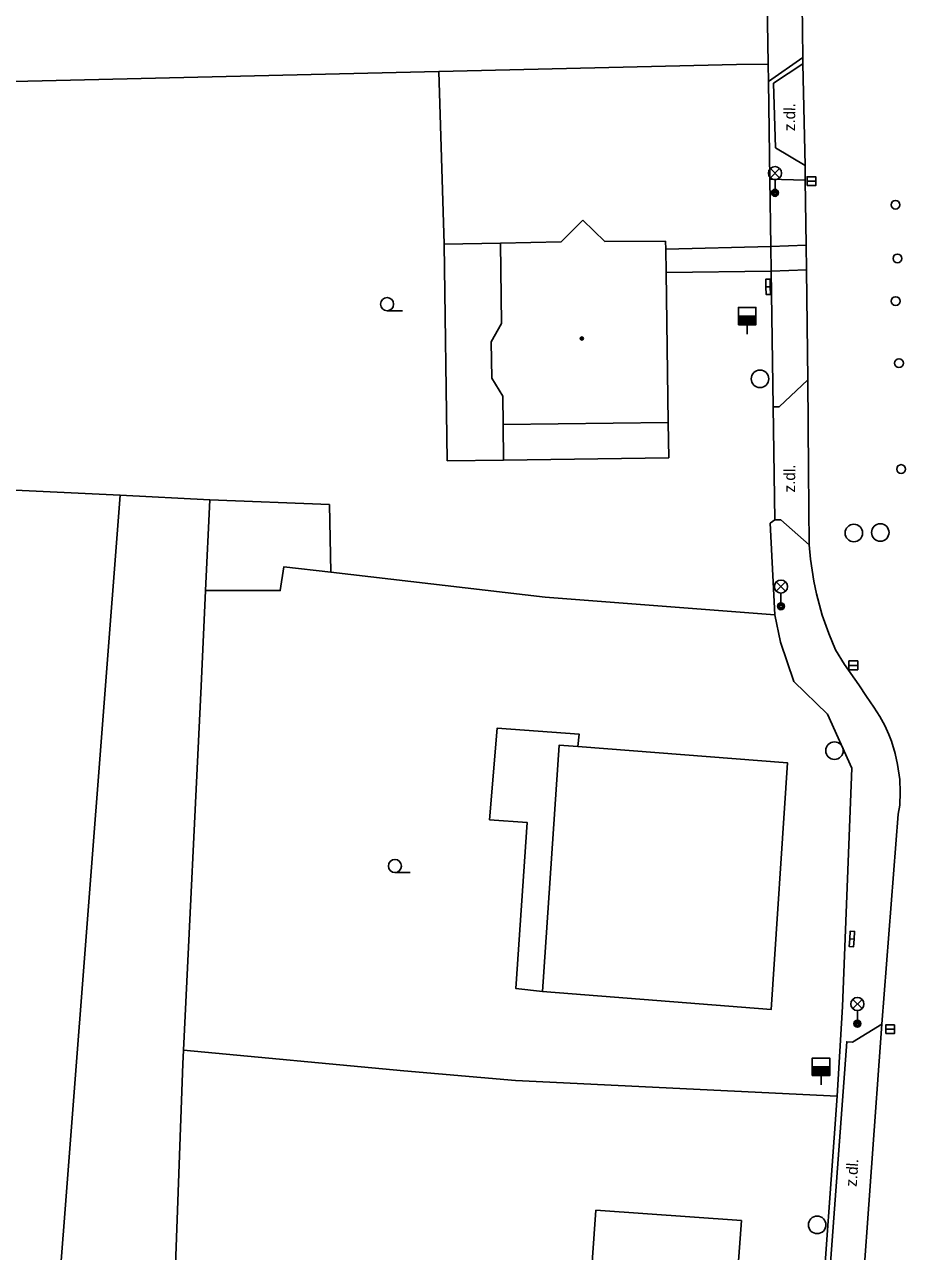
# Model space of a CAD drawing. Extents: x -595546 to -593986, y -1160845 to -1159202.
# Drawn here: x -594764.6 to -594714.2, y -1160222.4 to -1160152.3 of the extents above; entities that cross this region are included whole.
import ezdxf

# ---------------------------------------------------------------- set-up
doc = ezdxf.new("R2010")
doc.units = 0
for name, color, linetype in [('DOP - rozhrani ploch obecne', 7, 'Continuous'), ('Level 27', 7, 'Continuous'), ('Level 28', 7, 'Continuous'), ('Level 33', 7, 'Continuous'), ('Level 36', 7, 'Continuous'), ('Level 39', 7, 'Continuous'), ('plynovod - povrch.  znaky - PRIS skut. velikost', 7, 'Continuous'), ('silnoproud - povrch.  znaky a  RIS  skut. velikost', 7, 'Continuous'), ('TM - budovy zdene_ betonove - NP', 7, 'Continuous'), ('TM - budovy zdene_ betonove - VP', 7, 'Continuous'), ('TM - komunikace - VP', 7, 'Continuous'), ('TM - letecke snimky - pomocna linie', 7, 'Continuous'), ('TM - plot drateny_ kovovy - VP', 7, 'Continuous'), ('TM - popis povrchu', 7, 'Continuous'), ('TM - rozhrani ploch obecne - VP', 7, 'Continuous')]:
    doc.layers.add(name, color=color, linetype=linetype)

msp = doc.modelspace()

# ---------------------------------------------------------------- linework, layer by layer
at = {"layer": 'DOP - rozhrani ploch obecne'}
for points in [[(-594759.14, -1160179.18), (-594766.35, -1160178.84)], [(-594766.58, -1160275.71), (-594759.14, -1160179.18)], [(-594754, -1160179.45), (-594759.14, -1160179.18)], [(-594754.25, -1160184.64), (-594754, -1160179.45)], [(-594747.17, -1160179.72), (-594754, -1160179.45)], [(-594747.17, -1160179.72), (-594747.08, -1160183.59)], [(-594754.51, -1160190.11), (-594754.25, -1160184.64)], [(-594755.51, -1160210.93), (-594754.51, -1160190.11)], [(-594756.68, -1160242.61), (-594755.55, -1160211.71), (-594755.51, -1160210.93)]]:
    msp.add_lwpolyline(points, dxfattribs=at)
at = {"layer": 'Level 27'}
for p, q in [((-594719.85, -1160161.22), (-594719.35, -1160161.22)), ((-594717.45, -1160188.92), (-594716.95, -1160188.92)), ((-594715.35, -1160209.74), (-594714.85, -1160209.74))]:
    msp.add_line(p, q, dxfattribs=at)
for points in [[(-594719.85, -1160161.47), (-594719.35, -1160161.47), (-594719.35, -1160160.97), (-594719.85, -1160160.97)], [(-594717.45, -1160189.17), (-594716.95, -1160189.17), (-594716.95, -1160188.67), (-594717.45, -1160188.67)], [(-594715.35, -1160209.99), (-594714.85, -1160209.99), (-594714.85, -1160209.49), (-594715.35, -1160209.49)]]:
    msp.add_lwpolyline(points, close=True, dxfattribs=at)
for centre in [(-594722.54, -1160172.53), (-594717.17, -1160181.35), (-594715.66, -1160181.32), (-594718.28, -1160193.8), (-594719.27, -1160220.93)]:
    msp.add_circle(centre, 0.5, dxfattribs=at)
at = {"layer": 'Level 28'}
for p, q in [((-594723.77, -1160168.94), (-594722.77, -1160168.94)), ((-594723.77, -1160168.99), (-594722.77, -1160168.99)), ((-594723.77, -1160169.04), (-594722.77, -1160169.04)), ((-594723.77, -1160169.09), (-594722.77, -1160169.09)), ((-594723.77, -1160169.14), (-594722.77, -1160169.14)), ((-594723.77, -1160169.19), (-594722.77, -1160169.19)), ((-594723.77, -1160169.24), (-594722.77, -1160169.24)), ((-594723.77, -1160169.29), (-594722.77, -1160169.29)), ((-594723.77, -1160169.34), (-594722.77, -1160169.34)), ((-594723.77, -1160169.39), (-594722.77, -1160169.39)), ((-594723.27, -1160169.44), (-594723.27, -1160169.97)), ((-594719.55, -1160211.89), (-594718.55, -1160211.89)), ((-594719.55, -1160211.94), (-594718.55, -1160211.94)), ((-594719.55, -1160211.99), (-594718.55, -1160211.99)), ((-594719.55, -1160212.04), (-594718.55, -1160212.04)), ((-594719.55, -1160212.09), (-594718.55, -1160212.09)), ((-594719.55, -1160212.14), (-594718.55, -1160212.14)), ((-594719.55, -1160212.19), (-594718.55, -1160212.19)), ((-594719.55, -1160212.24), (-594718.55, -1160212.24)), ((-594719.55, -1160212.29), (-594718.55, -1160212.29)), ((-594719.55, -1160212.34), (-594718.55, -1160212.34)), ((-594719.05, -1160212.39), (-594719.05, -1160212.92))]:
    msp.add_line(p, q, dxfattribs=at)
for points in [[(-594723.77, -1160169.44), (-594722.77, -1160169.44), (-594722.77, -1160168.44), (-594723.77, -1160168.44)], [(-594719.55, -1160212.39), (-594718.55, -1160212.39), (-594718.55, -1160211.39), (-594719.55, -1160211.39)]]:
    msp.add_lwpolyline(points, close=True, dxfattribs=at)
for centre in [(-594714.79, -1160162.57), (-594714.68, -1160165.64), (-594714.78, -1160168.08), (-594714.59, -1160171.63), (-594714.47, -1160177.69)]:
    msp.add_circle(centre, 0.25, dxfattribs=at)
at = {"layer": 'Level 33'}
for p, q in [((-594721.945, -1160161.03), (-594721.415, -1160160.5)), ((-594721.945, -1160160.5), (-594721.415, -1160161.03)), ((-594721.68, -1160161.14), (-594721.68, -1160161.89)), ((-594721.605, -1160184.68), (-594721.075, -1160184.15)), ((-594721.605, -1160184.15), (-594721.075, -1160184.68)), ((-594721.34, -1160184.79), (-594721.34, -1160185.54)), ((-594717.235, -1160208.56), (-594716.705, -1160208.03)), ((-594717.235, -1160208.03), (-594716.705, -1160208.56)), ((-594716.97, -1160208.67), (-594716.97, -1160209.42))]:
    msp.add_line(p, q, dxfattribs=at)
for centre, radius in [((-594721.68, -1160160.765), 0.375), ((-594721.68, -1160161.89), 0.2), ((-594721.68, -1160161.89), 0.145), ((-594721.68, -1160161.89), 0.0876), ((-594721.34, -1160184.415), 0.375), ((-594721.34, -1160185.54), 0.2), ((-594721.34, -1160185.54), 0.145), ((-594721.34, -1160185.54), 0.0876), ((-594716.97, -1160208.295), 0.375), ((-594716.97, -1160209.42), 0.2), ((-594716.97, -1160209.42), 0.145), ((-594716.97, -1160209.42), 0.0876)]:
    msp.add_circle(centre, radius, dxfattribs=at)
at = {"layer": 'Level 36'}
for p, q in [((-594743.87, -1160168.635), (-594742.995, -1160168.635)), ((-594743.42, -1160200.775), (-594742.545, -1160200.775))]:
    msp.add_line(p, q, dxfattribs=at)
for centre in [(-594743.87, -1160168.26), (-594743.42, -1160200.4)]:
    msp.add_circle(centre, 0.375, dxfattribs=at)
at = {"layer": 'Level 39'}
for radius in [0.09, 0.0398]:
    msp.add_circle((-594732.73, -1160170.22), radius, dxfattribs=at)
at = {"layer": 'plynovod - povrch.  znaky - PRIS skut. velikost'}
for points in [[(-594722.2, -1160167.26), (-594721.95, -1160167.26)], [(-594721.95, -1160167.26), (-594721.94, -1160167.7), (-594722.19, -1160167.7), (-594722.2, -1160167.26)], [(-594717.16, -1160204.58), (-594717.19, -1160205.02), (-594717.44, -1160205), (-594717.41, -1160204.56)], [(-594717.41, -1160204.56), (-594717.16, -1160204.58)]]:
    msp.add_lwpolyline(points, dxfattribs=at)
at = {"layer": 'silnoproud - povrch.  znaky a  RIS  skut. velikost'}
for points in [[(-594721.95, -1160167.26), (-594721.95, -1160166.82), (-594722.2, -1160166.82), (-594722.2, -1160167.26)], [(-594717.41, -1160204.56), (-594717.38, -1160204.12), (-594717.13, -1160204.14), (-594717.16, -1160204.58)]]:
    msp.add_lwpolyline(points, dxfattribs=at)
at = {"layer": 'TM - budovy zdene_ betonove - NP'}
msp.add_lwpolyline([(-594737.23, -1160175.15), (-594727.79, -1160175.02)], dxfattribs=at)
at = {"layer": 'TM - budovy zdene_ betonove - VP'}
for points in [[(-594733.92, -1160164.7), (-594732.68, -1160163.46)], [(-594732.68, -1160163.46), (-594731.41, -1160164.68)], [(-594737.38, -1160164.76), (-594733.92, -1160164.7)], [(-594737.32, -1160169.36), (-594737.38, -1160164.76)], [(-594731.41, -1160164.68), (-594727.94, -1160164.65)], [(-594727.94, -1160164.65), (-594727.93, -1160165.11)], [(-594727.93, -1160165.11), (-594727.91, -1160166.45)], [(-594727.91, -1160166.45), (-594727.79, -1160175.02)], [(-594737.91, -1160170.41), (-594737.32, -1160169.36)], [(-594737.87, -1160172.49), (-594737.91, -1160170.41)], [(-594737.25, -1160173.52), (-594737.87, -1160172.49)], [(-594737.23, -1160175.15), (-594737.25, -1160173.52)], [(-594737.2, -1160177.18), (-594737.23, -1160175.15)], [(-594727.79, -1160175.02), (-594727.76, -1160177.05)], [(-594727.76, -1160177.05), (-594737.2, -1160177.18)], [(-594733.2, -1160238.22), (-594731.93, -1160220.09)], [(-594731.93, -1160220.09), (-594723.6, -1160220.67)], [(-594723.6, -1160220.67), (-594724.34, -1160230.73)]]:
    msp.add_lwpolyline(points, dxfattribs=at)
at = {"layer": 'TM - komunikace - VP'}
for points in [[(-594720.08, -1160154.15), (-594720.14, -1160149.56)], [(-594720.08, -1160154.51), (-594720.08, -1160154.15)], [(-594719.96, -1160160.33), (-594720.08, -1160154.51)], [(-594719.95, -1160161.16), (-594719.96, -1160160.33)], [(-594719.9, -1160164.89), (-594719.95, -1160161.16)], [(-594719.88, -1160166.3), (-594719.9, -1160164.89)], [(-594719.8, -1160172.58), (-594719.88, -1160166.3)], [(-594719.72, -1160182.03), (-594719.77, -1160177.76), (-594719.8, -1160172.58)], [(-594715.57, -1160209.44), (-594714.64, -1160197.43), (-594714.55, -1160196.91), (-594714.52, -1160196.17), (-594714.55, -1160195.45), (-594714.67, -1160194.59), (-594714.81, -1160193.96), (-594715.02, -1160193.26), (-594715.18, -1160192.87), (-594715.39, -1160192.37), (-594715.68, -1160191.85), (-594716.03, -1160191.31), (-594716.45, -1160190.7), (-594716.89, -1160190.04), (-594717.71, -1160188.88), (-594718.22, -1160188.03), (-594718.61, -1160187.1), (-594718.98, -1160186.05), (-594719.31, -1160184.83), (-594719.46, -1160184.1), (-594719.66, -1160182.84), (-594719.72, -1160182.03)], [(-594716.75, -1160225.85), (-594715.57, -1160209.44)]]:
    msp.add_lwpolyline(points, dxfattribs=at)
at = {"layer": 'TM - letecke snimky - pomocna linie'}
for points in [[(-594723.89, -1160154.55), (-594740.91, -1160154.95)], [(-594722.06, -1160155.52), (-594720.08, -1160154.15)], [(-594740.91, -1160154.95), (-594767.67, -1160155.57)], [(-594740.61, -1160164.82), (-594740.91, -1160154.95)], [(-594721.98, -1160161.11), (-594719.95, -1160161.16)], [(-594727.93, -1160165.11), (-594721.92, -1160164.95)], [(-594721.92, -1160164.95), (-594719.9, -1160164.89)], [(-594727.91, -1160166.45), (-594721.9, -1160166.37)], [(-594721.9, -1160166.37), (-594719.88, -1160166.3)], [(-594721.7, -1160186.04), (-594721.96, -1160180.79), (-594721.69, -1160180.59)], [(-594747.08, -1160183.59), (-594749.77, -1160183.28), (-594749.98, -1160184.64), (-594754.25, -1160184.64)], [(-594721.7, -1160186.04), (-594734.82, -1160185.02), (-594747.08, -1160183.59)], [(-594717.83, -1160208.43), (-594717.28, -1160194.81), (-594718.67, -1160191.72), (-594720.6, -1160189.85), (-594721.36, -1160187.6), (-594721.7, -1160186.04)], [(-594732.95, -1160193.57), (-594732.88, -1160192.86), (-594737.57, -1160192.51), (-594738.01, -1160197.75), (-594735.86, -1160197.91), (-594736.5, -1160207.41), (-594734.98, -1160207.57)], [(-594734.98, -1160207.57), (-594734.02, -1160193.48), (-594732.95, -1160193.57)], [(-594732.95, -1160193.57), (-594720.96, -1160194.5), (-594721.9, -1160208.6), (-594734.98, -1160207.57)], [(-594736.52, -1160212.67), (-594742.91, -1160212.11), (-594755.51, -1160210.93)], [(-594719.13, -1160227.6), (-594718.13, -1160213.56)]]:
    msp.add_lwpolyline(points, dxfattribs=at)
at = {"layer": 'TM - plot drateny_ kovovy - VP'}
for points in [[(-594717.83, -1160208.43), (-594718.13, -1160213.56)], [(-594718.13, -1160213.56), (-594736.52, -1160212.67)]]:
    msp.add_lwpolyline(points, dxfattribs=at)
at = {"layer": 'TM - rozhrani ploch obecne - VP'}
for points in [[(-594722.17, -1160148.55), (-594722.08, -1160154.52)], [(-594723.89, -1160154.55), (-594722.08, -1160154.52)], [(-594722.08, -1160154.52), (-594722.06, -1160155.52)], [(-594719.96, -1160160.33), (-594721.65, -1160159.31), (-594721.76, -1160155.62), (-594720.08, -1160154.51)], [(-594722.06, -1160155.52), (-594721.98, -1160161.11)], [(-594721.98, -1160161.11), (-594721.92, -1160164.95)], [(-594740.61, -1160164.82), (-594737.38, -1160164.76)], [(-594737.2, -1160177.18), (-594740.43, -1160177.22), (-594740.61, -1160164.82)], [(-594721.92, -1160164.95), (-594721.9, -1160166.37)], [(-594721.9, -1160166.37), (-594721.78, -1160174.14)], [(-594719.8, -1160172.58), (-594721.45, -1160174.13), (-594721.78, -1160174.14)], [(-594721.78, -1160174.14), (-594721.69, -1160180.59)], [(-594721.69, -1160180.59), (-594721.34, -1160180.6), (-594719.72, -1160182.03)], [(-594716.75, -1160225.85), (-594718.69, -1160225.7), (-594717.58, -1160210.45), (-594717.25, -1160210.47), (-594715.57, -1160209.44)]]:
    msp.add_lwpolyline(points, dxfattribs=at)

# ---------------------------------------------------------------- texts
at = {"layer": 'TM - popis povrchu'}
for rotation, p in [(89.81, (-594720.53, -1160158.36)), (89.81, (-594720.53, -1160179.03)), (86.21, (-594717.01, -1160218.76))]:
    msp.add_text('z.dl.', height=0.65, rotation=rotation, dxfattribs=at).set_placement(p)

doc.saveas('drawing.dxf')
